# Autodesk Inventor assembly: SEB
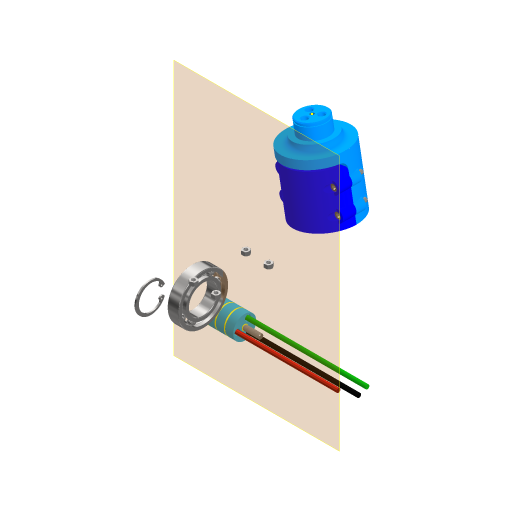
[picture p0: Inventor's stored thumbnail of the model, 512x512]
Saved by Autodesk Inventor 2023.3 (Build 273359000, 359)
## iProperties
Created: 2023-11
Part Number: SEB
Document SubType Name: Assembly
Designer: Thier
Author: Thier
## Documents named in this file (13)
- C:\Travail\BTS TechCom\2-TechnoIndus\21-Meca\214-Systémes Industriels-SI\2141-Pièces Ecrites\21411-Cycle1\214112-TP02Eolienne\2141122-DossierTechniqueEolienne\21411223-Maquette numerique\214112232-CEB-Eolienne\SEB.iam
- C:\Travail\BTS TechCom\2-TechnoIndus\21-Meca\214-Systémes Industriels-SI\2141-Pièces Ecrites\21411-Cycle1\214112-TP02Eolienne\2141122-DossierTechniqueEolienne\21411223-Maquette numerique\214112232-CEB-Eolienne\04-Corps de Pivot.ipt
- C:\Travail\BTS TechCom\2-TechnoIndus\21-Meca\214-Systémes Industriels-SI\2141-Pièces Ecrites\21411-Cycle1\214112-TP02Eolienne\2141122-DossierTechniqueEolienne\21411223-Maquette numerique\214112232-CEB-Eolienne\02-DIN 625 SKF - SKF 6007-2Z.ipt
- C:\Travail\BTS TechCom\2-TechnoIndus\21-Meca\214-Systémes Industriels-SI\2141-Pièces Ecrites\21411-Cycle1\214112-TP02Eolienne\2141122-DossierTechniqueEolienne\21411223-Maquette numerique\214112232-CEB-Eolienne\05-NF E 22-165 - 35x1,75.ipt
- C:\Travail\BTSTEC~1\2-TECH~1\21-Meca\214-SY~1\2141-P~1\21411-~1\214112~1\214112~2\214112~3\214112~2\DISQUE~1\20N-DI~1.IAM
- C:\Travail\BTS TechCom\2-TechnoIndus\21-Meca\214-Systémes Industriels-SI\2141-Pièces Ecrites\21411-Cycle1\214112-TP02Eolienne\2141122-DossierTechniqueEolienne\21411223-Maquette numerique\214112232-CEB-Eolienne\Disque collecteur\20p-Disque Collecteur Phase.iam
- C:\Travail\BTS TechCom\2-TechnoIndus\21-Meca\214-Systémes Industriels-SI\2141-Pièces Ecrites\21411-Cycle1\214112-TP02Eolienne\2141122-DossierTechniqueEolienne\21411223-Maquette numerique\214112232-CEB-Eolienne\Disque collecteur\20t-Disque collecteur Terre.iam
- C:\Travail\BTS TechCom\2-TechnoIndus\21-Meca\214-Systémes Industriels-SI\2141-Pièces Ecrites\21411-Cycle1\214112-TP02Eolienne\2141122-DossierTechniqueEolienne\21411223-Maquette numerique\214112232-CEB-Eolienne\23-Rondelle isolante.ipt
- C:\Travail\BTS TechCom\2-TechnoIndus\21-Meca\214-Systémes Industriels-SI\2141-Pièces Ecrites\21411-Cycle1\214112-TP02Eolienne\2141122-DossierTechniqueEolienne\21411223-Maquette numerique\214112232-CEB-Eolienne\19-Tube isolant.ipt
- C:\Travail\BTS TechCom\2-TechnoIndus\21-Meca\214-Systémes Industriels-SI\2141-Pièces Ecrites\21411-Cycle1\214112-TP02Eolienne\2141122-DossierTechniqueEolienne\21411223-Maquette numerique\214112232-CEB-Eolienne\06-MachoireDePivot.ipt
- C:\Travail\BTS TechCom\2-TechnoIndus\21-Meca\214-Systémes Industriels-SI\2141-Pièces Ecrites\21411-Cycle1\214112-TP02Eolienne\2141122-DossierTechniqueEolienne\21411223-Maquette numerique\214112232-CEB-Eolienne\26-ISO 4032 - M5NF EN.ipt
- C:\Travail\BTS TechCom\2-TechnoIndus\21-Meca\214-Systémes Industriels-SI\2141-Pièces Ecrites\21411-Cycle1\214112-TP02Eolienne\2141122-DossierTechniqueEolienne\21411223-Maquette numerique\214112232-CEB-Eolienne\27-NF E 25-125 - M5 x 30.ipt
- C:\Travail\BTS TechCom\2-TechnoIndus\21-Meca\214-Systémes Industriels-SI\2141-Pièces Ecrites\21411-Cycle1\214112-TP02Eolienne\2141122-DossierTechniqueEolienne\21411223-Maquette numerique\214112232-CEB-Eolienne\25-NF E 25-130 - M6 x 55A.ipt
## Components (20 placed, 12 different names)
1. 04-Corps de Pivot:1 — Angle:2, Logement:50, Logement:51
2. NF E 22-165 35x1,75:1
3. 20p-Disque Collecteur Phase:1 [sub-assembly] — Logement:38, Logement:39, Logement:44, Logement:45
4. 20t-Disque collecteur Terre:1 [sub-assembly] — Logement:42, Logement:43
5. 23-Rondelle isolante:1 — Logement:40, Logement:41, Logement:44, Logement:45
6. 23-Rondelle isolante:2 — Logement:38, Logement:39, Logement:48, Logement:49
7. 23-Rondelle isolante:3 — Logement:42, Logement:43, Logement:46, Logement:47
8. 19-Tube isolant:1 — Logement:49
9. 06-MachoireDePivot:1 — Logement:17, Logement:18, Logement:19, Logement:20, Logement:50, Logement:51
10. NF E 25-125 M5 x 30:4 — Logement:20
11. NF E 25-125 M5 x 30:3 — Logement:19
12. NF E 25-125 M5 x 30:2 — Logement:18
13. NF E 25-125 M5 x 30:1 — Logement:17
14. NF EN 24032 M5:1
15. NF EN 24032 M5:4
16. NF EN 24032 M5:5
17. NF EN 24032 M5:6
18. 20N-DI~1:1 [sub-assembly] — Logement:40, Logement:41, Logement:46, Logement:47
19. DIN 625 SKF- avec deux flasques Z SKF 6007-2Z:1
20. NF E 25-130 - A M6 x 55:1 — Logement:48
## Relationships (19: Insert 18, Angle 1)
- Logement:17 [Insert]: 06-MachoireDePivot:1 ↔ NF E 25-125 M5 x 30:1
- Logement:18 [Insert]: 06-MachoireDePivot:1 ↔ NF E 25-125 M5 x 30:2
- Logement:19 [Insert]: 06-MachoireDePivot:1 ↔ NF E 25-125 M5 x 30:3
- Logement:20 [Insert]: 06-MachoireDePivot:1 ↔ NF E 25-125 M5 x 30:4
- Angle:2: 04-Corps de Pivot:1
- Logement:38 [Insert]: 20p-Disque Collecteur Phase:1 ↔ 23-Rondelle isolante:2
- Logement:39 [Insert]: 20p-Disque Collecteur Phase:1 ↔ 23-Rondelle isolante:2
- Logement:40 [Insert]: 23-Rondelle isolante:1 ↔ 20N-DI~1:1
- Logement:41 [Insert]: 23-Rondelle isolante:1 ↔ 20N-DI~1:1
- Logement:42 [Insert]: 20t-Disque collecteur Terre:1 ↔ 23-Rondelle isolante:3
- Logement:43 [Insert]: 20t-Disque collecteur Terre:1 ↔ 23-Rondelle isolante:3
- Logement:44 [Insert]: 20p-Disque Collecteur Phase:1 ↔ 23-Rondelle isolante:1
- Logement:45 [Insert]: 20p-Disque Collecteur Phase:1 ↔ 23-Rondelle isolante:1
- Logement:46 [Insert]: 23-Rondelle isolante:3 ↔ 20N-DI~1:1
- Logement:47 [Insert]: 23-Rondelle isolante:3 ↔ 20N-DI~1:1
- Logement:48 [Insert]: 23-Rondelle isolante:2 ↔ NF E 25-130 - A M6 x 55:1
- Logement:49 [Insert]: 23-Rondelle isolante:2 ↔ 19-Tube isolant:1
- Logement:50 [Insert]: 04-Corps de Pivot:1 ↔ 06-MachoireDePivot:1
- Logement:51 [Insert]: 04-Corps de Pivot:1 ↔ 06-MachoireDePivot:1
